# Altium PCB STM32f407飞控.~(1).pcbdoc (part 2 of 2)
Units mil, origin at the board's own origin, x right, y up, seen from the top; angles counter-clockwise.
Board outline 2007.87 x 2007.87 mil, 2 copper layers (Top Layer, Bottom Layer); 91 components, 90 nets, 406 pads, 329 vias.
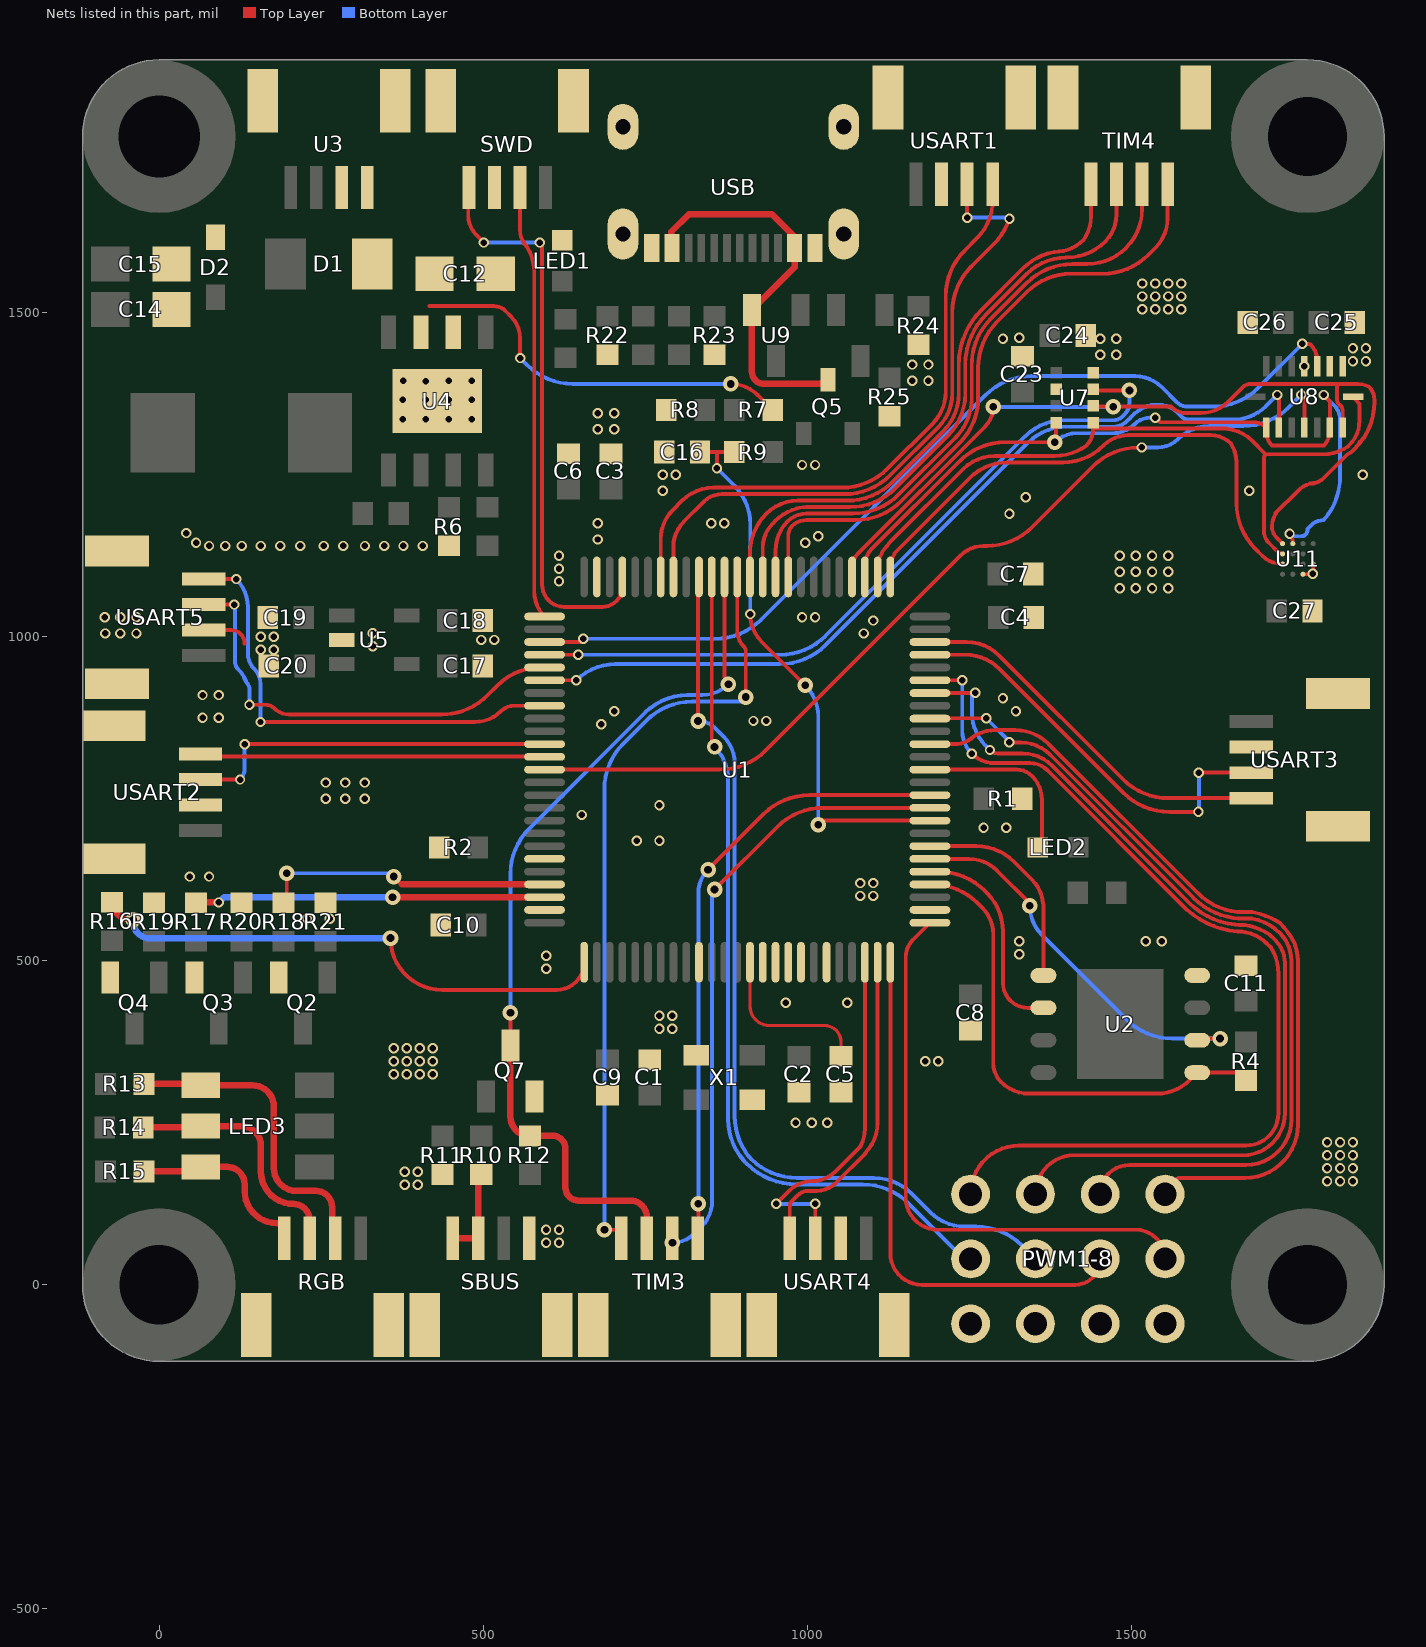
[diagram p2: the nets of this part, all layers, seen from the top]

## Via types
v1: diameter 16, hole 10, Top Layer to Bottom Layer, 269 vias
v2: diameter 31.5, hole 19.69, Top Layer to Bottom Layer, 32 vias
v3: diameter 24, hole 12, Top Layer to Bottom Layer, 23 vias
v4: diameter 24.02, hole 12.01, Top Layer to Bottom Layer, 5 vias

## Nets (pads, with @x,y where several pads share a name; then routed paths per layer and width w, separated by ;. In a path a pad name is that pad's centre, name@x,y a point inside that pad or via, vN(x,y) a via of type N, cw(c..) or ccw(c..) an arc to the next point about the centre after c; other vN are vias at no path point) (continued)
GND: C1.1 C2.1 C3.1 C4.1 C5.1 C6.1 C7.1 C8.1 C9.1 C10.1 C11.2 C12.2 C14.2 C15.2 C16.2 C17.2 C18.1 C19.2 C20.1 C23.1 C24.2 C25.2 C26.2 C27.2 D2.2 LED1.1 PWM1-8.9 PWM1-8.10 PWM1-8.11 PWM1-8.12 Q2.2 Q3.2 Q4.2 Q7.2 R1.2 R2.2 R6.1 R8.1 R11.2 R19.1 R20.1 R21.1 R22.2 R23.2 R24.1 R25.1 RGB.5 RGB.6 SBUS.4 SBUS.5 SBUS.6 SWD.3 SWD.5 SWD.6 TIM3.5 TIM3.6 TIM4.5 TIM4.6 U1.10 U1.20 U1.27 U1.74 U1.99 U2.4 U3.1 U3.2 U3.5 U3.6 U4.6 U4.9 U5.2 U7.1 U7.7 U8.4 U8.6 U8.7 U11.C1 U11.D1 U11.D2 USART1.3 USART1.5 USART1.6 USART2.3 USART2.5 USART2.6 USART3.3 USART3.5 USART3.6 USART4.3 USART4.5 USART4.6 USART5.3 USART5.5 USART5.6 USB.1 USB.12 USB.13 USB.14 X1.2 X1.4 | length 118.1
  Top Layer w6: USART5.3@68.82,1010.07 110.89,1010.07 cw(c110.89,989.07) 131.89,989.07 ; SWD.3@517.2,1680.88 SWD.3@517.2,1692.83 ; USART4.3@1051.58,71.69 ccw(c1051.58,72) USART4.3@1051.89,72 ; U11.C1@1764.76,1096.14 1778.43,1096.14 ccw(c1778.43,1098.16) v1(1779.85,1096.73) ccw(c1778.27,1098.32) 1780.51,1098.32 U11.D2@1780.51,1111.89
  other v1: 596.89,64.76 616.89,64.76 596.89,84.76 616.89,84.76 378.85,154.17 398.85,154.17 1801.89,159.76 1821.89,159.76 1841.89,159.76 378.85,174.17 398.85,174.17 1801.89,179.76 1821.89,179.76 1841.89,179.76 1801.89,199.76 1821.89,199.76 1841.89,199.76 1801.89,219.76 1821.89,219.76 1841.89,219.76 981.86,249.73 1006.89,249.76 1030.69,249.76 361.89,324.76 381.89,324.76 401.89,324.76 421.89,324.76 361.89,344.76 381.89,344.76 401.89,344.76 421.89,344.76 1181.89,344.76 1201.89,344.76 361.89,364.76 381.89,364.76 401.89,364.76 421.89,364.76 771.89,394.76 791.89,394.76 771.89,414.76 791.89,414.76 966.89,434.76 1061.35,434.76 597.18,487.52 597.18,507.52 1326.89,509.76 1326.89,529.76 1521.89,529.76 1546.89,529.76 228.19,564.76 263.19,564.76 1081.89,599.76 1101.89,599.76 1081.89,619.76 1101.89,619.76 46.89,629.76 76.89,629.76 736.89,684.76 771.89,684.76 1271.89,704.76 1306.89,704.76 651.89,724.76 771.89,739.76 256.89,749.76 286.89,749.76 316.89,749.76 256.89,774.76 286.89,774.76 316.89,774.76 681.89,864.76 916.89,869.76 936.89,869.76 66.89,874.76 91.89,874.76 701.89,884.76 1321.89,884.76 1301.89,904.76 66.89,909.76 91.89,909.76 156.89,979.76 176.89,979.76 329.26,985.32 496.89,994.76 516.89,994.76 156.89,999.76 176.89,999.76 -83.11,1004.76 -60.03,1004.76 -35.03,1004.76 329.26,1005.32 1086.89,1004.76 1101.89,1024.76 -83.91,1029.76 -60.03,1029.76 -35.03,1029.76 991.89,1029.76 1011.89,1029.76 1481.89,1074.76 1506.89,1074.76 1531.89,1074.76 1556.89,1074.76 616.89,1085.26 1481.89,1099.76 1506.89,1099.76 1531.89,1099.76 1556.89,1099.76 616.89,1104.76 616.89,1124.76 1481.89,1124.76 1506.89,1124.76 1531.89,1124.76 1556.89,1124.76 76.89,1139.76 101.89,1139.76 127.19,1139.76 156.89,1139.76 186.89,1139.76 217.63,1139.76 253.93,1139.76 283.93,1139.76 317.54,1139.76 347.54,1139.76 376.89,1139.76 406.89,1139.76 56.89,1144.76 996.89,1144.76 676.89,1149.76 1016.89,1154.76 41.89,1159.76 676.89,1174.76 851.89,1174.76 871.89,1174.76 1311.89,1189.76 1336.89,1214.76 776.89,1224.76 1681.89,1224.76 776.89,1249.76 796.89,1249.76 1856.89,1249.76 991.89,1264.76 1011.89,1264.76 676.89,1319.76 701.89,1319.76 375.93,1335.22 411.02,1335.22 446.89,1335.22 481.89,1335.22 676.89,1344.76 701.89,1344.76 375.93,1365.22 411.02,1365.22 446.89,1365.22 481.89,1365.22 411.02,1394 376.89,1394.76 446.89,1394.76 481.89,1394.76 1161.89,1394.76 1186.89,1394.76 1766.97,1417 1161.89,1419.76 1186.89,1419.76 1841.89,1424.76 1861.89,1424.76 1451.89,1434.76 1476.89,1434.76 1841.89,1444.76 1861.89,1444.76 1301.89,1459.76 1451.89,1459.76 1476.89,1459.76 1327,1460.82 1516.89,1504.76 1536.89,1504.76 1556.89,1504.76 1576.89,1504.76 1516.89,1524.76 1536.89,1524.76 1556.89,1524.76 1576.89,1524.76 1516.89,1544.76 1536.89,1544.76 1556.89,1544.76 1576.89,1544.76
GYR_INT: U1.88 U8.12 | length 1434.8
  Top Layer w6: U1.88@594.65,794.76 864.82,794.76 ccw(c864.82,894.76) 935.53,824.05 1236.64,1125.16 cw(c1271.89,1089.91) 1271.89,1139.76 1276.33,1139.76 ccw(c1276.33,1239.76) 1347.04,1169.05 1440.44,1262.45 cw(c1511.15,1191.74) 1511.15,1291.74 v1(1515.87,1291.74) ; v1(1761.89,1372.76) 1766.97,1367.68 U8.12@1766.97,1322.52
  Bottom Layer w6: v1(1515.87,1291.74) 1540.45,1291.74 ccw(c1540.45,1336.2) 1571.89,1304.76 cw(c1620.17,1256.48) 1620.17,1324.76 1672.47,1324.76 ccw(c1672.47,1424.76) 1743.18,1354.05 v1(1761.89,1372.76)
LED_1: R18.1 U1.97 | length 452.3
  Top Layer w6: R18.1@191.89,589.42 196.89,594.42 v3(196.89,634.76) ; v3(361.89,629.76) 374.06,617.59
  Top Layer w10: 374.06,617.59 U1.97@594.65,617.59
  Bottom Layer w6: v3(196.89,634.76) 356.89,634.76 v3(361.89,629.76)
LED_2: R17.1 U1.98 | length 541.3
  Top Layer w10: R17.1@56.89,589.42 cw(c57.23,589.42) 57.23,589.76 v1(91.89,589.76) ; v4(360.04,597.91) U1.98@594.65,597.91
  Bottom Layer w10: v1(91.89,589.76) 100.04,597.91 v4(360.04,597.91)
LED_3: R16.1 U1.1 | length 831
  Top Layer w6: v4(356.89,534.76) ccw(c436.89,534.76) 436.89,454.76 612.91,454.76 ccw(c612.91,497.52) U1.1@655.67,497.52
  Top Layer w10: R16.1@-73.11,590.1 -73.11,589.76 ccw(c-43,593.06) v4(-39.94,562.93)
  Bottom Layer w10: v4(-39.94,562.93) ccw(c-14.79,559.89) -18.11,534.76 v4(356.89,534.76)
LED_4: LED2.1 U1.38 | length 276.3
  Top Layer w6: U1.38@1189.13,794.76 1322.75,794.76 cw(c1322.75,760.62) 1346.89,784.76 cw(c1310.68,748.55) 1361.89,748.55 1361.89,690.26 cw(c1339.78,690.26) LED2.1@1355.41,674.63
LED_B: LED3.1 R13.2 RGB.3 | length 490.3
  Top Layer w10: R13.2@-23.45,309.76 62.18,309.76 cw(c62.18,307.75) LED3.1@64.19,307.75 143.9,307.75 cw(c143.9,274.76) 176.89,274.76 176.89,179.76 ccw(c211.89,179.76) 211.89,144.76 241.89,144.76 cw(c241.89,119.76) 266.89,119.76 266.89,76.38 ccw(c271.58,76.38) RGB.3@271.58,71.69
LED_G: LED3.2 R14.2 RGB.2 | length 385.8
  Top Layer w10: R14.2@-24.52,242.6 62.03,242.6 ccw(c62.03,244.76) LED3.2@64.19,244.76 126.89,244.76 cw(c126.89,214.76) 156.89,214.76 156.89,174.76 ccw(c206.89,174.76) 206.89,124.76 cw(c206.89,99.44) 232.21,99.44 RGB.2@232.21,71.69
LED_R: LED3.3 R15.2 RGB.1 | length 263.3
  Top Layer w10: R15.2@-23.45,174.76 57.18,174.76 ccw(c57.18,181.77) LED3.3@64.19,181.77 104.88,181.77 cw(c104.88,154.76) 131.89,154.76 131.89,144.76 ccw(c181.89,144.76) 181.89,94.76
NRST: C5.2 U1.14 | length 261.8
  Top Layer w5: U1.14@911.58,497.52 911.58,430.07 ccw(c941.89,430.07) 941.89,399.76 1026.89,399.76 cw(c1026.89,374.76) 1051.89,374.76 C5.2@1051.89,352.32
POWER_ADC: C16.1 R9.1 U1.34 | length 859
  Top Layer w6: C16.1@834.45,1284.76 858.54,1284.76 ; v1(860.59,1259.76) 860.59,1282.72 858.54,1284.76 ; R9.1@887.23,1284.76 858.54,1284.76 ; v1(911.89,1034.76) ccw(c972.25,1034.76) 929.57,992.09 v3(996.89,924.76) ; v3(1016.89,709.76) 1023.15,716.02 U1.34@1189.13,716.02
  Bottom Layer w6: v1(860.59,1259.76) 887.27,1233.09 cw(c827.82,1173.64) 911.89,1173.64 v1(911.89,1034.76) ; v3(996.89,924.76) cw(c948.61,876.48) 1016.89,876.48 v3(1016.89,709.76)
SBUS_IN: R10.2 SBUS.1 SBUS.2 | length 140.5
  Top Layer w10: SBUS.1@452.84,71.69 SBUS.2@492.21,71.69 492.21,165.42 cw(c496.89,165.42) R10.2@496.89,170.1
SPI1_MISO: U1.31 U2.2 | length 606.8
  Top Layer w6: U1.31@1189.13,656.96 1248.97,656.96 cw(c1248.97,594.86) 1292.88,638.77 1343.34,588.31 v3(1343.34,584.76) ; U2.2@1601.56,377.22 1604.1,379.76 v3(1636.89,379.76)
  Bottom Layer w6: v3(1343.34,584.76) ccw(c1407.2,584.76) 1362.04,539.61 1492.6,409.05 ccw(c1563.31,479.76) 1563.31,379.76 v3(1636.89,379.76)
SPI1_MOSI: U1.32 U2.5 | length 327.8
  Top Layer w6: U1.32@1189.13,676.65 1260.63,676.65 cw(c1260.63,593.68) 1319.3,652.35 1346.13,625.52 cw(c1302.17,581.56) 1363.87,589.17 cw(c1343.34,584.76) 1364.34,584.76 cw(c1343.34,584.76) 1364.31,583.59 cw(c1302.17,581.56) 1364.34,581.56 U2.5@1364.34,477.22
SPI1_NSS: R4.1 U1.29 U2.1 | length 766.2
  Top Layer w6: U1.29@1189.13,617.59 1192.64,617.59 cw(c1192.64,517.59) 1263.35,588.3 1269.59,582.06 cw(c1227.82,540.3) 1286.89,540.3 1286.89,341.98 ccw(c1328.45,341.98) 1299.06,312.59 ccw(c1342.1,355.63) 1342.1,294.76 1539.47,294.76 ccw(c1539.47,366.31) 1590.06,315.72 U2.1@1601.56,327.22 1664.77,327.22 R4.1@1676.89,315.1
SPI1_SCK: U1.30 U2.6 | length 327.1
  Top Layer w6: U1.30@1189.13,637.28 1202.95,637.28 cw(c1202.95,537.28) 1273.66,607.99 1277.18,604.47 cw(c1217.53,544.82) 1301.89,544.82 1301.89,465.54 ccw(c1339.99,465.54) 1313.05,438.61 ccw(c1340.54,466.09) 1340.54,427.22 U2.6@1364.34,427.22
SPI2_CS1: U1.81 U8.14 | length 1362.3
  Top Layer w6: U1.81@594.65,932.56 v1(643.76,932.56) ; v1(1724.82,1372.76) 1727.6,1369.98 U8.14@1727.6,1322.52
  Bottom Layer w6: v1(1724.82,1372.76) 1707.98,1355.93 cw(c1656.89,1407.02) 1656.89,1334.76 1588.96,1334.76 cw(c1588.96,1351.83) 1576.89,1339.76 1571.18,1345.47 ccw(c1541.97,1316.25) 1541.97,1357.57 1531.11,1357.57 ccw(c1547.48,1294.05) 1504.98,1344.02 ccw(c1547.49,1294.05) 1501.1,1340.43 1498.88,1338.21 cw(c1470.57,1360.97) 1496.25,1335.29 cw(c1468.43,1363.1) 1494.93,1334.02 cw(c1471.89,1354.76) 1471.89,1323.76 cw(c1471.89,1354.76) 1470.27,1323.81 cw(c1468.43,1363.1) 1468.43,1323.76 1400.45,1323.76 ccw(c1400.45,1238.27) 1339.99,1298.72 1028.12,986.85 cw(c957.41,1057.56) 957.41,957.56 704.11,957.56 ccw(c704.11,872.21) v1@643.89,932.7 ; v1@643.89,932.7 ccw(c704.13,872.23) v1(643.76,932.56) v1@643.89,932.7
SPI2_CS2: U1.78 U8.5 | length 1431.1
  Top Layer w6: U1.78@594.65,991.61 649.3,991.61 v1(654.3,996.61) ; v1(1763.65,1451.52) 1772.64,1451.52 cw(c1772.64,1445.52) 1776.89,1449.76 cw(c1753.3,1426.18) 1786.66,1426.18 U8.5@1786.66,1417
  Bottom Layer w6: v1(654.3,996.61) 857.62,996.61 ccw(c857.62,1096.61) 928.33,1025.9 1274.9,1372.47 cw(c1345.61,1301.76) 1345.61,1401.76 1505.85,1401.76 cw(c1505.85,1343.72) 1546.89,1384.76 1569.82,1361.83 ccw(c1586.89,1378.91) 1586.89,1354.76 1625.47,1354.76 ccw(c1625.47,1454.76) 1696.18,1384.05 v1(1763.65,1451.52)
SPI2_CS3: U1.79 U7.2 | length 1135.2
  Top Layer w6: U1.79@594.65,971.93 v1(646.3,971.93) ; U7.2@1440.96,1381.42 1442.61,1379.76 v3(1496.89,1379.76)
  Bottom Layer w6: v1(646.3,971.93) 957.64,971.93 ccw(c957.64,1071.93) 1028.35,1001.22 1336.13,1309 cw(c1395.91,1249.22) 1395.91,1333.76 1468.43,1333.76 ccw(c1468.43,1363.1) 1470.31,1333.82 ccw(c1471.89,1354.76) 1471.89,1333.76 ccw(c1471.89,1354.76) 1487.82,1341.08 ccw(c1468.43,1363.11) 1489.18,1342.36 ccw(c1470.57,1360.97) 1496.89,1360.97 v3(1496.89,1379.76)
SPI2_MISO: U1.53 U7.5 U8.10 U8.15 U11.B4 | length 1252.7
  Top Layer w6: U1.53@1088.74,1092 1088.74,1109.64 cw(c1124.69,1109.64) 1099.27,1135.06 1234.68,1270.47 cw(c1305.39,1199.76) 1305.39,1299.76 1383.88,1299.76 U7.5@1383.88,1330.24 U7.5@1386.89,1327.22 ; v1(1536.89,1337.76) 1543.89,1330.76 1688.03,1330.76 cw(c1688.03,1302.63) U8.15@1707.92,1322.52 1707.92,1316.42 ccw(c1738.55,1316.42) 1716.89,1294.76 1796.89,1294.76 ccw(c1774.08,1317.58) 1806.34,1317.58 1806.34,1362.96 v1(1796.53,1372.76) ; v1(1744.02,1158.38) cw(c1731.95,1146.31) 1749.02,1146.31 U11.B4@1749.02,1143.38
  Bottom Layer w6: v3(1381.89,1299.76) cw(c1415.69,1265.96) 1415.69,1313.76 1471.41,1313.76 ccw(c1471.42,1360.76) 1471.66,1313.76 ccw(c1471.88,1354.77) 1471.89,1313.76 ccw(c1471.89,1354.76) 1478.57,1314.31 ccw(c1471.41,1360.78) 1504.66,1327.54 cw(c1529.35,1302.84) 1529.35,1337.76 v1(1536.89,1337.76) ; v1(1744.02,1158.38) 1747.54,1154.86 1757.42,1154.86 ; 1760.5,1154.86 ccw(c1761.89,1164.76) 1771.79,1166.16 1777.25,1171.62 cw(c1796.48,1152.39) 1796.48,1179.58 ccw(c1721.89,1246.19) 1821.49,1237.2 ccw(c1804.89,1240.89) 1821.89,1240.89 ccw(c1804.89,1240.89) 1821.82,1242.43 ccw(c1721.89,1246.19) 1821.89,1246.19 1821.89,1335.04 ccw(c1792.05,1335.04) 1813.15,1356.15 v1(1796.53,1372.76)
SPI2_MOSI: U1.54 U7.3 U8.9 U11.A4 | length 1402.8
  Top Layer w6: U1.54@1069.06,1092 1069.06,1107.35 cw(c1097.17,1107.35) 1077.29,1127.23 1274.48,1324.42 ccw(c1244.53,1354.37) 1286.89,1354.37 v3(1286.89,1354.76) ; U7.3@1440.96,1355.84 1442.03,1354.76 v3(1471.89,1354.76) 1561.09,1354.76 ccw(c1585.23,1378.91) 1585.23,1344.76 1606.89,1344.76 ccw(c1606.89,1405.12) 1649.57,1362.44 1671.72,1384.59 cw(c1684.2,1372.12) 1684.2,1389.76 1817.53,1389.76 ; 1722.59,1190.46 1756.91,1224.78 cw(c1788.17,1193.53) 1775.72,1235.94 ; 1723.06,1189.98 ccw(c1753.1,1169.76) 1716.89,1169.76 ccw(c1741.03,1169.76) 1723.96,1152.69 U11.A4@1733.27,1143.38 ; 1820.16,1358.49 cw(c1826.53,1364.84) 1817.53,1364.84 1817.53,1389.76 ; 1820.18,1358.47 ccw(c1826.53,1364.84) 1822.6,1356.75 cw(c1814.33,1348.47) 1824.48,1354.3 cw(c1814.33,1348.47) 1826.03,1348.47 U8.9@1826.03,1322.52 ; 1775.72,1235.94 ccw(c1775.72,1265.76) 1785.7,1237.66 ; 1775.72,1235.94 cw(c1788.17,1193.52) 1785.7,1237.66 ; 1785.7,1237.66 ccw(c1775.72,1265.76) 1796.8,1244.68 1832.99,1280.87 ccw(c1796,1347.45) 1839.85,1285.17 ccw(c1834.09,1293.34) 1841.16,1286.27 1843.75,1288.86 ; 1817.53,1389.76 1849.73,1389.76 cw(c1849.73,1354.08) 1866.66,1385.49 cw(c1846.61,1365.45) 1874.96,1365.45 1874.96,1361.5 cw(c1775,1361.49) 1874.96,1361.29 cw(c1774.96,1361.5) 1858.2,1306.07 ; 1843.75,1288.86 ccw(c1799.96,1332.65) 1853.28,1301.16 1858.2,1306.07 ; 1843.75,1288.86 1845.67,1290.79 ccw(c1774.96,1361.5) 1858.2,1306.07
  Bottom Layer w6: v3(1286.89,1354.76) 1287.43,1354.23 1471.35,1354.23 v3(1471.89,1354.76)
SPI2_NSS: U1.51 U11.A2 | length 847.4
  Top Layer w6: U1.51@1128.11,1092 1128.11,1101.43 cw(c1187.38,1101.43) 1134.68,1128.56 1251.36,1245.24 cw(c1308.15,1188.46) 1308.15,1268.76 1394.29,1268.76 ccw(c1394.29,1357.13) 1456.77,1294.65 cw(c1495.68,1255.73) 1495.68,1310.76 1622.05,1310.76 cw(c1622.05,1266.24) 1653.54,1297.72 cw(c1610.81,1269.33) 1662.11,1269.33 1662.11,1205.97 ccw(c1762.11,1205.97) 1691.4,1135.26 1701.89,1124.76 ccw(c1732.96,1155.83) 1732.96,1111.89 U11.A2@1733.27,1111.89
SPI2_SCK: U1.52 U7.4 U8.8 U11.A3 | length 1117.5
  Top Layer w6: U1.52@1108.43,1092 1108.43,1104.19 cw(c1160.02,1104.19) 1123.54,1140.66 cw(c1179.68,1096.79) 1129.3,1147.17 1240.59,1258.47 cw(c1289.6,1209.46) 1289.6,1278.76 1381.82,1278.76 ccw(c1381.82,1361.01) 1430.41,1294.65 ccw(c1404.95,1320.11) 1440.96,1320.11 U7.4@1440.96,1330.24 ; 1441.89,1321.33 1442.22,1321.66 1442.22,1320.76 1645.89,1320.76 cw(c1645.89,1310.76) 1648.73,1320.35 cw(c1641.55,1257.93) 1685.98,1302.36 1707.09,1281.25 ccw(c1713.27,1275.13) 1704.58,1275.13 1704.58,1162.42 ccw(c1729.55,1162.42) 1711.89,1144.76 1726.01,1130.64 ccw(c1733.27,1137.89) U11.A3@1733.27,1127.63 ; 1707.12,1281.28 1796,1281.28 ccw(c1796,1347.45) 1834.09,1293.34 1836.68,1295.94 ccw(c1799.96,1332.65) 1851.89,1332.65 1851.89,1358.73 ccw(c1771.89,1298.73) 1842.6,1369.44 U8.8@1842.28,1369.76
SWCLK: SWD.2 U1.76 | length 671.1
  Top Layer w6: SWD.2@556.57,1692.83 556.57,1628.22 ccw(c595.91,1628.22) 560.72,1610.63 ccw(c595.91,1628.22) 568.09,1600.4 cw(c504.36,1562.23) 578.65,1562.23 578.65,1069.61 ccw(c633.28,1069.61) U1.76@594.65,1030.98
SWDIO: SWD.4 U1.72 | length 885.1
  Top Layer w6: SWD.4@477.83,1692.83 ccw(c480.1,1690.56) 476.89,1690.56 476.89,1649.76 ccw(c519.82,1649.76) 489.46,1619.4 v1(500.89,1607.98) ; v1(587.01,1607.98) 590.76,1604.23 590.76,1080.54 ccw(c626.11,1080.54) 601.11,1055.54 ccw(c624.41,1078.84) 624.41,1045.89 683.81,1045.89 ccw(c683.81,1076.8) 714.72,1076.8 U1.72@714.72,1092
  Bottom Layer w6: v1(500.89,1607.98) v1(587.01,1607.98)
TIM1_CH1: PWM1-8.4 U1.40 | length 1256.3
  Top Layer w6: U1.40@1189.13,834.13 1227.31,834.13 ccw(c1227.31,878.3) 1231.53,834.34 ccw(c1227.31,878.3) 1247.95,839.26 ; PWM1-8.4@1551.89,139.76 cw(c1576.89,139.76) 1576.89,164.76 1675.17,164.76 ccw(c1675.17,246.48) 1756.89,246.48 1756.89,499.58 ccw(c1686.08,499.58) 1740.13,545.32 ccw(c1666.53,492.9) 1730.43,556.79 1729.02,558.2 ccw(c1673.9,474.76) 1706.91,569.16 ccw(c1672.64,486.13) 1688.09,574.61 ccw(c1686.37,564.76) 1686.37,574.76 1673.31,574.76 cw(c1673.31,674.76) 1602.6,604.05 1372.32,834.34 ccw(c1320.59,782.61) 1320.59,855.76 1290.49,855.76 ccw(c1290.49,792.71) 1269.84,852.29 ccw(c1290.49,792.71) 1258.54,847.07 ; 1247.95,839.26 ccw(c1227.31,878.3) 1258.54,847.07 ; 1247.95,839.26 cw(c1290.49,792.71) 1258.54,847.07
TIM1_CH2: PWM1-8.3 U1.42 | length 1320.9
  Top Layer w6: U1.42@1189.13,873.5 1189.62,874 v1(1276.06,874) ; v1(1311.82,836.76) 1328.78,836.76 cw(c1328.78,771.65) 1345.68,834.53 cw(c1328.78,771.65) 1374.82,817.69 1595.53,596.98 ; PWM1-8.3@1451.89,139.76 cw(c1496.89,139.76) 1496.89,184.76 1676.89,184.76 ccw(c1676.89,254.76) 1746.89,254.76 1746.89,499.58 ccw(c1686.08,499.58) 1729.08,542.58 ccw(c1672.64,486.13) 1686.37,564.76 1673.31,564.76 cw(c1673.31,674.76) 1657.18,565.95 cw(c1673.31,674.76) 1595.57,596.94
  Bottom Layer w6: v1(1276.06,874) 1311.82,838.24 v1(1311.82,836.76)
TIM1_CH3: PWM1-8.2 U1.44 | length 1445.7
  Top Layer w6: U1.44@1189.13,912.87 1258.83,912.87 v1(1259.06,913.11) ; v1(1281.82,825) ccw(c1294.45,837.63) 1294.45,819.76 1331.89,819.76 cw(c1331.89,755.27) 1377.5,800.87 1589.32,589.05 ccw(c1673.31,674.76) 1659.9,555.52 ccw(c1673.31,674.76) 1673.31,554.76 1674.36,554.76 cw(c1662.7,464.7) 1713.72,539.82 1722.16,531.39 cw(c1686.59,495.82) 1736.89,495.82 1736.89,264.76 cw(c1671.89,264.76) 1671.89,199.76 1411.89,199.76 ccw(c1411.89,139.76) PWM1-8.2@1351.89,139.76
  Bottom Layer w6: v1(1259.06,913.11) 1254.06,908.11 1254.06,882.57 ccw(c1326.04,882.57) 1275.14,831.67 v1(1281.82,825)
TIM1_CH4: PWM1-8.1 U1.45 | length 1544.8
  Top Layer w6: U1.45@1189.13,932.56 1238.83,932.56 v1(1239.06,932.8) ; PWM1-8.1@1251.89,139.76 cw(c1326.89,139.76) 1326.89,214.76 1676.89,214.76 ccw(c1676.89,264.76) 1726.89,264.76 1726.89,479.76 ccw(c1650.83,479.76) 1715.34,520.06 1709.32,526.08 ccw(c1663.27,480.03) 1669.97,544.81 cw(c1673.31,674.76) 1663.27,545.15 cw(c1673.31,674.76) 1585.34,579.05 ; v1(1253.55,819.48) ccw(c1289.09,855.01) 1289.09,804.76 1343.96,804.76 cw(c1343.96,767.34) 1370.43,793.8 1585.12,579.11 ccw(c1585.26,579.25) 1585.26,579.05
  Bottom Layer w6: v1(1239.06,932.8) 1239.06,854.48 ccw(c1288.55,854.48) v1(1253.55,819.48)
TIM3_CH1: TIM3.1 U1.63 | length 1200.3
  Top Layer w6: v3(686.89,84.76) 712.84,84.76 TIM3.1@712.84,71.69 ; U1.63@891.89,1092 891.89,1008.91 ccw(c926.03,1008.91) 901.89,984.76 cw(c894.16,977.04) 905.09,977.04 v3(905.09,906.56)
  Bottom Layer w6: v3(686.89,84.76) 686.89,764.2 cw(c786.89,764.2) 716.18,834.91 751.74,870.47 cw(c822.45,799.76) 822.45,899.76 898.29,899.76 v3(905.09,906.56)
TIM3_CH2: Q7.3 R12.2 TIM3.2 U1.64 | length 1369.9
  Top Layer w6: Q7.3@541.89,369.13 v3(541.89,419.76) ; U1.64@872.21,1092 872.21,941.05 ccw(c892.7,941.05) v3(878.21,926.56)
  Top Layer w10: Q7.3@541.89,369.13 541.89,259.42 ccw(c571.89,259.42) R12.2@571.89,229.42 cw(c572.23,229.42) 572.23,229.76 606.89,229.76 cw(c606.89,209.76) 626.89,209.76 626.89,149.76 ccw(c646.89,149.76) 646.89,129.76 726.89,129.76 cw(c726.89,104.44) 752.21,104.44 TIM3.2@752.21,71.69
  Bottom Layer w6: v3(541.89,419.76) 541.89,633.34 cw(c641.89,633.34) 571.18,704.05 749.64,882.52 cw(c815.42,816.73) 815.42,909.76 837.65,909.76 ccw(c837.65,967.12) v3(878.21,926.56)
TIM3_CH3: TIM3.3 U1.35 | length 959.3
  Top Layer w6: v3(856.89,609.76) 953.54,706.41 ; 953.57,706.44 cw(c1024.25,635.7) 1024.25,735.7 U1.35@1189.13,735.7
  Bottom Layer w6: v3(791.89,64.76) ccw(c791.89,113.05) 826.03,78.91 836.89,89.76 ccw(c798.26,128.39) 851.01,114.19 ccw(c798.26,128.39) 852.07,118.94 ccw(c831.89,124.76) 852.89,124.76 ccw(c831.89,124.76) 852.84,126.15 ccw(c798.26,128.39) 852.89,128.39 852.89,605.76 v3(856.89,609.76)
TIM3_CH4: TIM3.4 U1.36 | length 958.7
  Top Layer w6: TIM3.4@830.95,71.69 831.89,72.63 v3(831.89,124.76) ; v3(846.89,640.39) 932.6,726.1 cw(c1003.31,655.39) 1003.31,755.39 U1.36@1189.13,755.39
  Bottom Layer w6: v3(831.89,124.76) 831.89,604.18 cw(c883.1,604.18) v3(846.89,640.39)
TIM4_CH1: TIM4.1 U1.59 | length 974.2
  Top Layer w6: U1.59@970.63,1092 970.63,1156.16 cw(c991.14,1156.16) 976.64,1170.66 cw(c998.62,1148.67) 998.62,1179.76 1074.27,1179.76 ccw(c1074.27,1279.76) 1144.98,1209.05 1235.32,1299.39 ; 1235.37,1299.44 ccw(c1166.95,1367.76) 1263.64,1367.76 1263.64,1415.09 cw(c1363.64,1415.09) 1292.93,1485.8 1338.61,1531.48 cw(c1406.89,1463.2) 1406.89,1559.76 1455.47,1559.76 ccw(c1455.47,1659.76) 1526.18,1589.05 1536.89,1599.76 ccw(c1490.9,1645.75) 1555.94,1645.75 TIM4.1@1555.94,1697.83
TIM4_CH2: TIM4.2 U1.60 | length 945.9
  Top Layer w6: U1.60@950.95,1092 950.95,1132.79 cw(c1014.51,1132.79) 969.57,1177.73 cw(c998.62,1148.67) 998.62,1189.76 1070.12,1189.76 ccw(c1070.12,1289.76) 1140.83,1219.05 1228.25,1306.46 ccw(c1166.95,1367.76) 1253.64,1367.76 1253.64,1419.23 cw(c1353.64,1419.23) 1254.53,1432.6 cw(c1353.64,1419.23) 1282.93,1489.94 1338.46,1545.47 cw(c1409.17,1474.76) 1409.17,1574.76 1431.53,1574.76 ccw(c1431.53,1660.12) 1491.89,1599.76 ccw(c1432.31,1659.35) 1516.57,1659.35 TIM4.2@1516.57,1697.83
TIM4_CH3: TIM4.3 U1.61 | length 924.4
  Top Layer w6: U1.61@931.26,1092 931.26,1137.03 cw(c984.62,1137.03) 946.89,1174.76 950.94,1178.81 cw(c1001.52,1128.23) 983.15,1197.37 cw(c998.62,1148.67) 998.62,1199.76 1065.47,1199.76 ccw(c1065.47,1299.76) 1136.18,1229.05 1216.47,1309.35 ; 1216.53,1309.4 ccw(c1150.9,1374.92) 1243.64,1374.92 1243.64,1419.23 cw(c1353.64,1419.23) 1243.96,1427.65 cw(c1353.63,1419.23) 1244.62,1433.94 cw(c1353.64,1419.23) 1249.81,1455.56 cw(c1353.64,1419.23) 1275.85,1497.01 1338.29,1559.44 cw(c1399.41,1498.32) 1399.41,1584.76 ccw(c1399.41,1670.43) 1459.99,1609.85 ccw(c1419.18,1650.66) 1476.89,1650.66 1476.89,1697.09 cw(c1477.95,1697.09) TIM4.3@1477.2,1697.83
TIM4_CH4: TIM4.4 U1.62 | length 910
  Top Layer w6: U1.62@911.58,1092 911.58,1128.66 cw(c997.99,1128.66) 911.89,1135.97 cw(c997.99,1128.66) 936.89,1189.76 cw(c985.17,1141.48) 985.17,1209.76 1061.33,1209.76 ccw(c1061.33,1309.76) 1132.04,1239.05 1209.4,1316.42 ; 1209.45,1316.47 ccw(c1150.9,1374.92) 1233.64,1374.92 1233.64,1424.98 cw(c1233.89,1424.98) 1233.71,1425.16 1233.79,1425.24 cw(c1353.63,1419.23) 1233.99,1428.42 cw(c1353.63,1419.23) 1234.71,1435.27 cw(c1353.64,1419.23) 1240.37,1458.87 cw(c1353.64,1419.23) 1268.78,1504.08 1333,1568.3 cw(c1396.89,1504.41) 1379.39,1593.05 1380.5,1593.05 ccw(c1380.5,1657.49) 1381.35,1593.06 cw(c1399.41,1498.32) 1394.77,1594.65 ccw(c1380.51,1657.48) 1395.19,1594.75 ccw(c1380.5,1657.49) 1426.07,1611.93 ccw(c1373.64,1648.96) 1437.83,1648.96 TIM4.4@1437.83,1697.83
TIM5_CH3: PWM1-8.6 U1.25 | length 823.9
  Top Layer w6: U1.25@1128.11,497.52 1128.11,48.54 ccw(c1176.89,48.54) 1176.89,-0.24 1412.86,-0.24 ccw(c1412.86,38.8) 1451.89,38.8 PWM1-8.6@1451.89,39.76
TIM5_CH4: PWM1-8.5 U1.26 | length 891.7
  Top Layer w6: U1.26@1189.13,558.54 1163.41,532.83 ccw(c1191.23,505.01) 1151.89,505.01 1151.89,134.76 ccw(c1201.89,134.76) 1201.89,84.76 1506.89,84.76 cw(c1506.89,39.76) PWM1-8.5@1551.89,39.76
TIM8_CH3: PWM1-8.8 U1.65 | length 1316.6
  Top Layer w6: U1.65@852.52,1092 852.52,834.07 v3(856.86,829.73)
  Bottom Layer w6: v3(856.86,829.73) cw(c806.07,778.95) 877.89,778.95 877.89,255.37 ccw(c974.6,255.37) 901.87,191.62 ccw(c987.89,260.18) 902.83,190.44 ccw(c910.56,196.78) 903.49,189.71 906.22,186.98 ccw(c984,264.76) 984,154.76 1085.47,154.76 cw(c1085.47,54.76) 1156.18,125.47 1234.82,46.83 ccw(c1251.89,63.91) PWM1-8.8@1251.89,39.76
TIM8_CH4: PWM1-8.7 U1.66 | length 1420.2
  Top Layer w6: v3(831.52,869.76) 831.52,1090.69 U1.66@832.83,1092
  Bottom Layer w6: v3(831.52,869.76) cw(c831.52,832.66) 857.76,858.9 870.8,845.85 cw(c829.55,804.6) 887.89,804.6 887.89,260.19 ccw(c987.89,260.19) 910.56,196.78 913.29,194.05 ccw(c984,264.76) 984,164.76 1101.89,164.76 cw(c1101.89,80.27) 1161.64,140.02 1190.04,111.62 ccw(c1242.79,164.38) 1242.79,89.76 1260.47,89.76 cw(c1260.47,-10.24) 1331.18,60.47 PWM1-8.7@1351.89,39.76
TIM10_CH1: U1.95
USART1_RX: U1.69 USART1.1 | length 953.8
  Top Layer w6: U1.69@773.78,1092 773.78,1150.17 cw(c837.72,1150.17) 792.51,1195.38 806.89,1209.76 cw(c855.17,1161.48) 855.17,1229.76 1053.04,1229.76 ccw(c1053.04,1329.76) 1123.75,1259.05 1192.85,1328.15 ccw(c1142.66,1378.34) 1213.64,1378.34 1213.64,1525.09 cw(c1313.64,1525.09) 1242.93,1595.8 1261.89,1614.76 ccw(c1203.83,1672.83) 1285.94,1672.83 USART1.1@1285.94,1697.83
USART1_TX: U1.68 USART1.2 | length 1010.9
  Top Layer w6: U1.68@793.46,1092 793.24,1092.22 793.24,1138.25 cw(c848.46,1138.25) 809.42,1177.29 840.31,1208.18 cw(c868.27,1180.22) 868.27,1219.76 1057.18,1219.76 ccw(c1057.18,1319.76) 1127.89,1249.05 1202.33,1323.49 ccw(c1150.9,1374.92) 1223.64,1374.92 1223.64,1500.09 cw(c1323.64,1500.09) 1252.93,1570.8 1287.6,1605.47 ccw(c1216.89,1676.19) v1(1311.88,1644.92) ; v1(1246.57,1646.42) USART1.2@1246.57,1697.83
  Bottom Layer w6: v1(1246.57,1646.42) 1308.25,1646.42 cw(c1308.25,1641.3) v1(1311.88,1644.92)
USART2_RX: U1.87 USART2.1 | length 532.1
  Top Layer w6: USART2.1@63.82,818.81 ccw(c73.6,828.59) 73.6,814.76 594.34,814.76 cw(c594.34,814.45) U1.87@594.65,814.45
USART2_TX: U1.86 USART2.2 | length 580.3
  Top Layer w6: USART2.2@63.82,779.44 v1(124.72,779.44) ; v1(131.89,834.13) U1.86@594.65,834.13
  Bottom Layer w6: v1(124.72,779.44) ccw(c107.42,796.74) 131.89,796.74 v1(131.89,834.13)
USART3_RX: U1.48 USART3.1 | length 588.3
  Top Layer w6: U1.48@1189.13,991.61 1246.02,991.61 cw(c1246.02,921.56) 1295.56,971.1 1486.65,780 ccw(c1557.36,850.71) 1557.36,750.71 USART3.1@1684.96,750.71
USART3_TX: U1.47 USART3.2 | length 631.9
  Top Layer w6: U1.47@1189.13,971.93 1243.8,971.93 cw(c1243.8,897.29) 1296.58,950.07 1487.91,758.74 ccw(c1558.62,829.45) 1558.62,729.45 v1(1603.52,729.45) ; v1(1604.06,790.08) USART3.2@1667.89,790.08
  Bottom Layer w6: v1(1603.52,729.45) ccw(c1602.24,730.74) 1604.06,730.74 v1(1604.06,790.08)
USART4_RX: U1.24 USART4.1 | length 498.8
  Top Layer w6: USART4.1@972.84,71.69 972.84,119.99 cw(c986.67,119.99) 976.89,129.76 984.82,137.69 cw(c1001.89,120.62) 1001.89,144.76 1014.16,144.76 ccw(c1014.16,187.56) 1044.43,157.3 1089.52,202.39 ; 1089.02,202.88 ccw(c1042.17,249.74) 1108.43,249.74 U1.24@1108.43,497.52
USART4_TX: U1.23 USART4.2 | length 561.1
  Top Layer w6: v1(951.89,124.76) 972.75,145.62 cw(c1006.89,111.48) 1006.89,159.76 ccw(c1006.89,211.43) 1043.43,174.9 1082.05,213.53 ccw(c1031.21,240.44) 1088.74,240.44 U1.23@1088.74,497.52 ; USART4.2@1012.21,71.69 v1(1012.21,124.8)
  Bottom Layer w6: v1(951.89,124.76) v1@1012.12,124.76
USART5_RX: U1.83 USART5.1 | length 725.6
  Top Layer w6: USART5.1@68.82,1088.81 v1(118.82,1088.81) ; v1(156.33,868.19) 486.89,868.19 ccw(c486.89,924.77) 526.89,884.76 cw(c547.24,864.41) 547.24,893.19 U1.83@594.65,893.19
  Bottom Layer w6: v1(118.82,1088.81) cw(c75.19,1045.19) 136.89,1045.19 136.89,973.91 ccw(c171.03,973.91) 146.89,949.76 cw(c124.1,926.97) 156.33,926.97 v1(156.33,868.19)
USART5_TX: U1.80 USART5.2 | length 689.5
  Top Layer w6: USART5.2@68.82,1049.44 v1(116.03,1049.44) ; v1(139.33,894.82) 164.69,894.82 cw(c164.69,877.57) 176.89,889.76 ccw(c200.91,913.78) 200.91,879.82 435.52,879.82 ccw(c435.52,979.82) 468.34,885.35 ccw(c435.52,979.82) 506.23,909.1 521.89,924.76 cw(c588.23,858.42) 588.23,952.24 U1.80@594.65,952.24
  Bottom Layer w6: v1(116.03,1049.44) cw(c113.96,1047.37) 116.89,1047.37 116.89,961.83 ccw(c133.96,961.83) 121.89,949.76 cw(c85.8,913.67) 133.91,930.7 cw(c120.84,917.63) 139.33,917.63 v1(139.33,894.82)
VBUS: Q5.3 U9.2 USB.2 USB.11 | length 604.3
  Top Layer w10: USB.11@791.33,1599.41 790.02,1600.72 790.02,1624.47 817.31,1651.76 945.48,1651.76 981.89,1615.36 981.89,1600.99 USB.2@980.31,1599.41 980.31,1569.96 U9.2@914.49,1504.13 914.49,1408.85 ccw(c933.55,1408.85) 933.55,1389.79 1020.37,1389.79 Q5.3@1026.89,1396.3
VCC_IN: C12.1 D1.1 R7.2 U4.7 | length 615.2
  Top Layer w6: 416.89,1509.76 516.89,1509.76 cw(c516.89,1485.62) 533.96,1502.69 542.8,1493.86 cw(c508.78,1459.83) 556.89,1459.83 v1(556.89,1429.76) ; v3(881.89,1389.76) cw(c881.89,1330.23) 923.99,1372.33 R7.2@946.55,1349.76
  Bottom Layer w6: v1(556.89,1429.76) 567.6,1419.05 ccw(c638.31,1489.76) 638.31,1389.76 v3(881.89,1389.76)
X_IO_1: U1.17
X_IO_2: U1.16
X_IO_3: U1.15
X_IO_4: U1.18
pads on no net: M1.1 M2.1 M3.1 M4.1 U1.2 U1.3 U1.4 U1.5 U1.7 U1.8 U1.9 U1.33 U1.39 U1.41 U1.43 U1.46 U1.55 U1.56 U1.57 U1.58 U1.67 U1.77 U1.82 U1.84 U1.85 U1.89 U1.90 U1.91 U1.92 U1.93 U1.96 U2.9 U4.2 U4.3 U4.5 U8.1 U8.2 U8.13 U8.16 U11.B3 U11.C2 U11.C3 USB.3 USB.9
copper on no net:
  other v2: 0,-90.86 1771.65,-90.86 -65.88,-65.38 66.88,-65.38 1705.77,-65.38 1838.53,-65.38 -93.36,0 91.36,0 1678.29,0 1863.01,0 64.88,63.38 1836.53,63.38 -66.38,64.88 1705.27,64.88 -0.5,89.86 1771.15,89.86 0,1679.29 1771.65,1680.79 -67.38,1704.27 67.38,1704.27 1705.77,1706.27 1838.53,1706.27 -92.36,1771.65 92.36,1771.65 1678.29,1771.65 1863.01,1771.65 67.38,1834.03 1836.53,1835.03 1705.27,1836.53 -62.38,1839.03 1771.15,1861.51 0,1864.01

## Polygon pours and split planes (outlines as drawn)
no net on Bottom Layer "NONET_L02_P035" (solid, pour order 35): -123.11,1906.89 -118.11,1911.89 1891.89,1911.89 1891.89,-138.11 1886.89,-143.11 -118.11,-143.11
+3V3 on Bottom Layer "Bottom Layer-+3V3" (solid, remove dead copper, pour order 28): 361.74,1080.71 472.04,1080.71 472.04,998.81 361.74,998.81
+3V3 on Bottom Layer "Bottom Layer-+3V3 1" (solid, remove dead copper, pour order 30): 605.75,1240.91 605.75,1175.91 ccw(c611.89,1175.91) 611.89,1169.76 643.52,1169.76 ccw(c643.52,1175.91) 649.67,1175.91 649.67,1236.99 ccw(c641.89,1236.99) 641.89,1244.76 609.84,1244.76 ccw(c609.84,1240.79) 605.87,1240.79 ccw(c605.75,1240.79)
+5V on Bottom Layer "Bottom Layer-+5V" (solid, pour order 32): -104.81,1640.94 7.6,1640.94 7.6,1508.35 -39.81,1460.94 -39.81,1445.94 -109.81,1445.94 -109.81,1635.94
no net on Top Layer "NONET_L01_P036" (solid, pour order 36): -123.11,1906.89 1841.89,1906.89 1896.89,1851.89 1896.89,-128.11 -128.11,-128.11
+3V3 on Top Layer "Top Layer-+3V3" (solid, remove dead copper, pour order 2): 361.89,1089.76 471.89,1089.76 471.89,999.81 361.89,999.81
$2N671 on Top Layer "Top Layer-$2N671" (solid, pour order 0): 336.23,1419.76 352.84,1419.76 371.89,1439.76 371.89,1504.76 125.19,1504.76 122.48,1502.05 122.48,1547.6 121.54,1548.54 65.46,1548.54 64.46,1547.53 64.46,1449.76 267.68,1449.76 267.68,1380.56 266.89,1379.76 196.91,1379.76 196.91,1249.76 301.89,1249.76 301.89,1284.76 336.89,1319.76 336.89,1419.1
+3V3 on Top Layer "Top Layer-+3V3 1" (solid, remove dead copper, pour order 4): 605.85,1240.91 605.85,1175.91 ccw(c612,1175.91) 612,1169.76 643.63,1169.76 ccw(c643.63,1175.91) 649.77,1175.91 649.77,1236.99 ccw(c642,1236.99) 642,1244.76 609.95,1244.76 ccw(c609.95,1240.79) 605.97,1240.79 ccw(c605.85,1240.79)
+3V3 on Top Layer "Top Layer-+3V3 2" (solid, remove dead copper, pour order 6): 461.89,579.08 461.89,477.23 534.36,477.23 ccw(c534.36,479.76) 536.89,479.76 536.89,574.76 ccw(c531.89,574.76) 531.89,579.76 462.57,579.76 ccw(c462.57,579.08)
+3V3 on Top Layer "Top Layer-+3V3 3" (solid, remove dead copper, pour order 8): 1206.89,464.76 1266.89,464.76 cw(c1266.89,459.76) 1271.89,459.76 1271.89,424.02 cw(c1267.64,424.02) 1267.64,419.76 1211.27,419.76 cw(c1211.27,424.02) 1207.02,424.02 cw(c1207.02,424.14) 1206.89,424.14
+3V3 on Top Layer "Top Layer-+3V3 4" (solid, remove dead copper, pour order 10): 1576.89,454.76 1576.89,402.22 1649.43,402.22 1656.89,394.76 1656.89,354.77 1660.37,351.29 1718.41,351.29 1721.89,354.76 1721.89,454.76
+3V3 on Top Layer "Top Layer-+3V3 5" (solid, remove dead copper, pour order 12): 1320.07,396.95 1384.71,396.95 cw(c1384.71,389.76) 1391.89,389.76 1391.89,314.76 cw(c1386.89,314.76) 1386.89,309.76 1321.89,309.76 cw(c1321.89,319.76) 1311.89,319.76 1311.89,388.77 cw(c1320.07,388.77)
+5V on Top Layer "Top Layer-+5V" (solid, remove dead copper, pour order 14): 1041.89,1334.76 1076.89,1334.76 cw(c1076.89,1329.76) 1081.89,1329.76 1081.89,1279.75 cw(c1076.89,1279.75) 1076.89,1274.75 1047.09,1274.75 cw(c1047.09,1279.75) 1042.09,1279.75 1042.09,1334.56 ccw(c1041.89,1334.56)
+5V on Top Layer "Top Layer-+5V 1" (solid, remove dead copper, pour order 16): 1023.57,1550.99 1024.8,1549.76 1061.89,1549.76 1061.89,1475.72 1019.8,1475.72 1019.8,1547.57 1023.4,1551.17
$2N276 on Top Layer "Top Layer-$2N276" (solid, remove dead copper, pour order 18): 184.46,1729.76 184.46,1648.2 118.63,1648.2 124.1,1526.98 121.89,1524.76 211.89,1524.76 216.89,1519.76 216.89,1579.76 226.89,1589.76 267.37,1589.76 267.64,1630.91 267.64,1729.76
VCC_IN on Top Layer "Top Layer-VCC_IN" (solid, remove dead copper, pour order 20): 306.89,1614.76 306.89,1529.76 381.89,1529.76 381.89,1434.76 376.89,1429.76 430.79,1429.76 430.79,1514.76 446.89,1514.76 456.89,1524.76 456.89,1614.76
+5V on Top Layer "Top Layer-+5V 2" (solid, remove dead copper, pour order 22): -108.11,1639.76 -108.11,1180.94 -13.91,1180.94 -13.91,1253.29 -12.43,1254.76 56.89,1254.76 56.89,1374.76 -43.11,1374.76 -43.11,1639.76
+3V3 on Top Layer "Top Layer-+3V3 6" (solid, remove dead copper, pour order 24): 1241.89,1114.76 1311.89,1114.76 1311.89,1074.71 1306.89,1074.76 1272.34,1075.05 1244.32,1075.05 1241.89,1074.76

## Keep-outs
Board Outline Layer:
  region: 1631.89,1559.76 1831.89,1559.76 1831.89,1536.14 1631.89,1536.14
  region: 1611.89,1559.76 1635.51,1559.76 1635.51,1394.76 1611.89,1394.76
  region: 1611.89,1272.26 1635.51,1272.26 1635.51,977.26 1611.89,977.26
  region: 1624.25,977.95 1624.25,1001.57 1829.25,1001.57 1829.25,977.95
  region: -13.91,1447.68 267.68,1447.68 267.68,1181.84 -13.91,1181.84
  lines w1: 1611.89,977.26 1635.51,977.26 1635.51,1272.26 1611.89,1272.26 1611.89,977.26 ; 1611.89,1394.76 1635.51,1394.76 1635.51,1559.76 1611.89,1559.76 1611.89,1394.76 ; 1624.25,977.95 1624.25,1001.57 1829.25,1001.57 1829.25,977.95 1624.25,977.95 ; 1631.89,1536.14 1831.89,1536.14 1831.89,1559.76 1631.89,1559.76 1631.89,1536.14
  lines w10: -118.11,0 ccw(c0,0) 0,-118.11 1771.65,-118.11 ccw(c1771.65,0) 1889.76,0 1889.76,1771.65 ccw(c1771.65,1771.65) 1771.65,1889.76 0,1889.76 ccw(c0,1771.65) -118.11,1771.65 -118.11,0

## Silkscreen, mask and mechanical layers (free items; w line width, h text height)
Top Silkscreen Layer:
  text "RTGV" at 1331.89,1674.76 h40 r180
  text "1234" at 1576.89,1674.76 h40 r180
  text "VCGD" at 586.89,1659.76 h40 r180
  text "-" at 366.89,1634.75 h40
  text "+" at 96.89,1609.76 h40
  text "AUX2" at 1586.89,1604.76 h40 r180
  text "RTGV" at -38.11,1124.76 h40 r270
  text "RTGV" at 81.89,904.76 h40 r270
  text "RTGV" at 1636.89,714.76 h40 r90
  text "AUX1" at 666.89,184.76 h40
  text "1234" at 686.89,109.76 h40
  text "RTGV" at 930.95,104.76 h40
  text "RGBV" at 261.89,99.76 h40
  text "II VG" at 461.89,99.76 h40
  text "RGBV" at 176.19,-19.62 h40
Bottom Silkscreen Layer:
  drawing of 20 lines, arcs and shapes, not listed
Mechanical Layer:
  lines w1: 1611.89,977.26 1635.51,977.26 1635.51,1272.26 1611.89,1272.26 1611.89,977.26 ; 1611.89,1394.76 1635.51,1394.76 1635.51,1559.76 1611.89,1559.76 1611.89,1394.76 ; 1624.25,977.95 1624.25,1001.57 1829.25,1001.57 1829.25,977.95 1624.25,977.95 ; 1631.89,1536.14 1831.89,1536.14 1831.89,1559.76 1631.89,1559.76 1631.89,1536.14
Mechanical 6:
  text "2007.874 (mil)" at 499.95,2043.77 h40
  text "1771.654 (mil)" at 509.95,1913.77 h40
  text "122.047 (mil)" at 2180.85,1420.75 h40 r90
  text "1771.654 (mil)" at -137.12,509.95 h40 r90
  text "2007.874 (mil)" at -297.12,499.95 h40 r90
